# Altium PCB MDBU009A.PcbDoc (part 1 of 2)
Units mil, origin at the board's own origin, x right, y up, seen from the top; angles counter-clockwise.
Board outline 2000 x 3000 mil, 2 copper layers (Top Layer, Bottom Layer), stack 63.4 mil thick; 59 components, 52 nets, 252 pads, 189 vias.
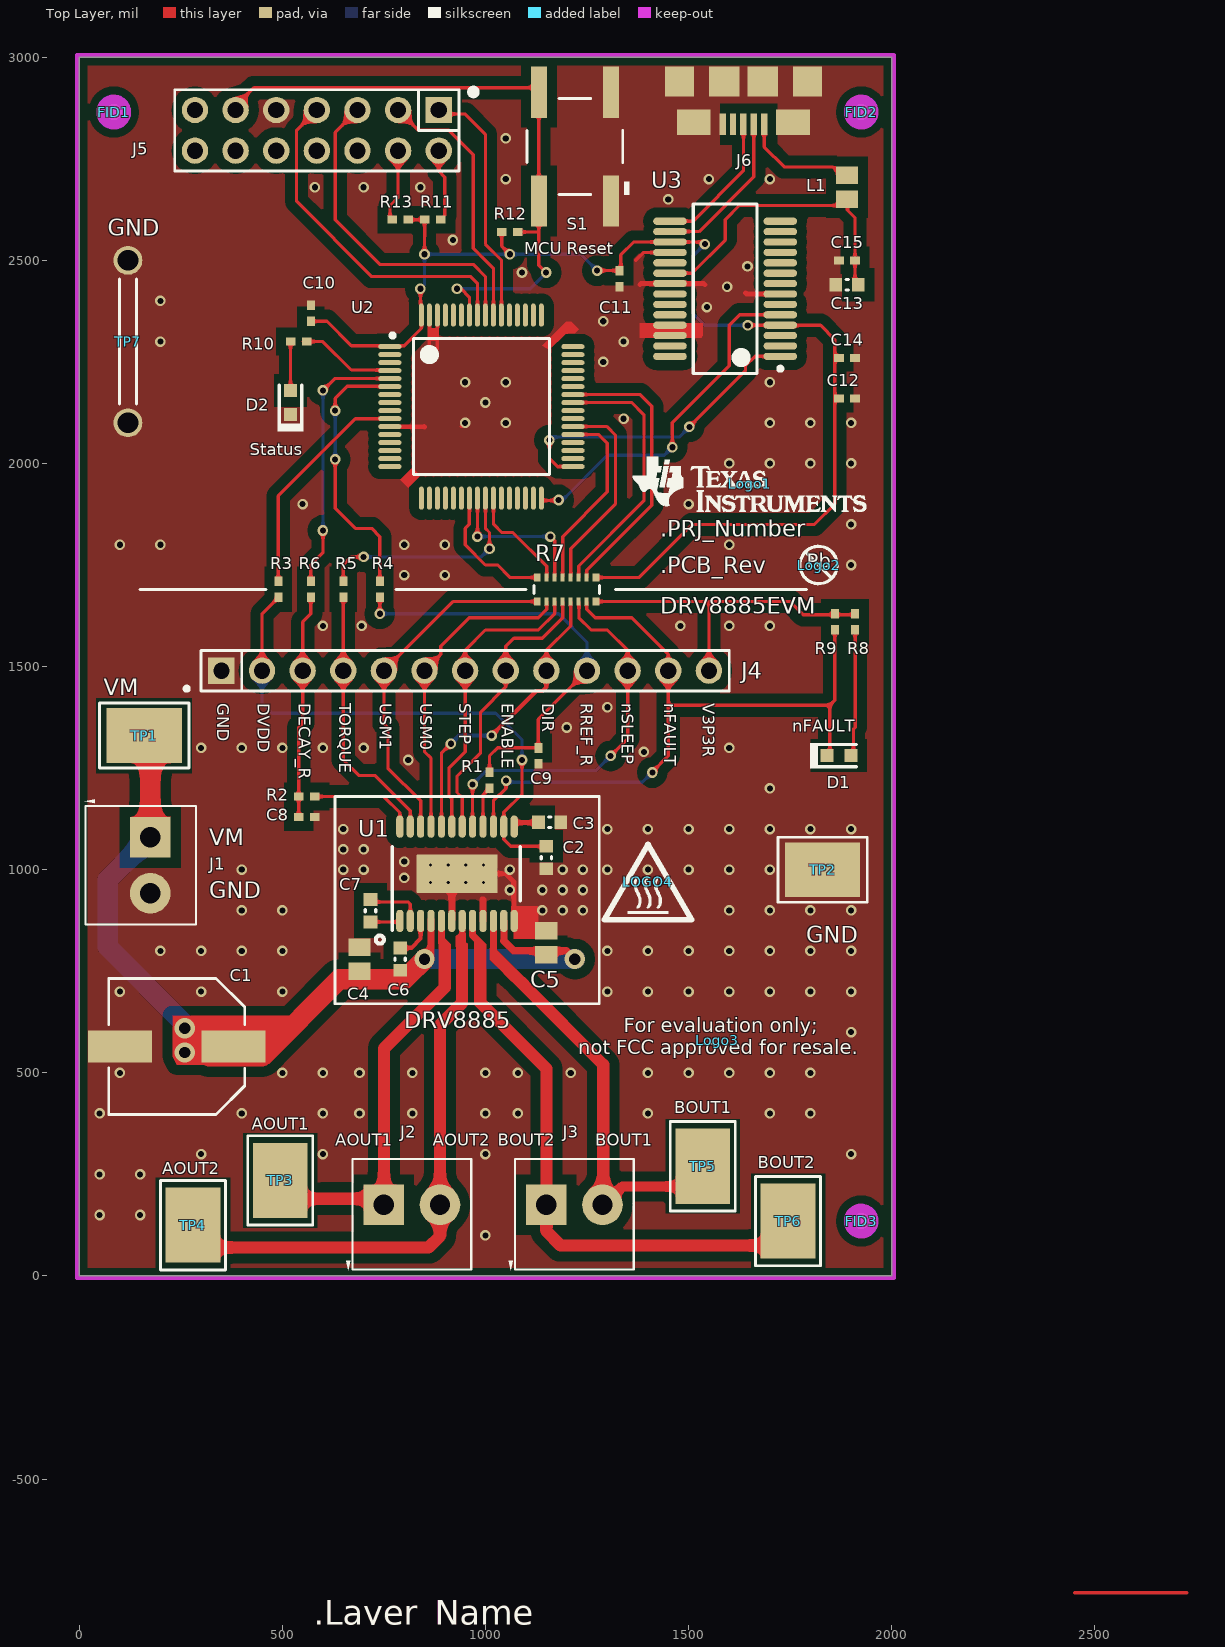
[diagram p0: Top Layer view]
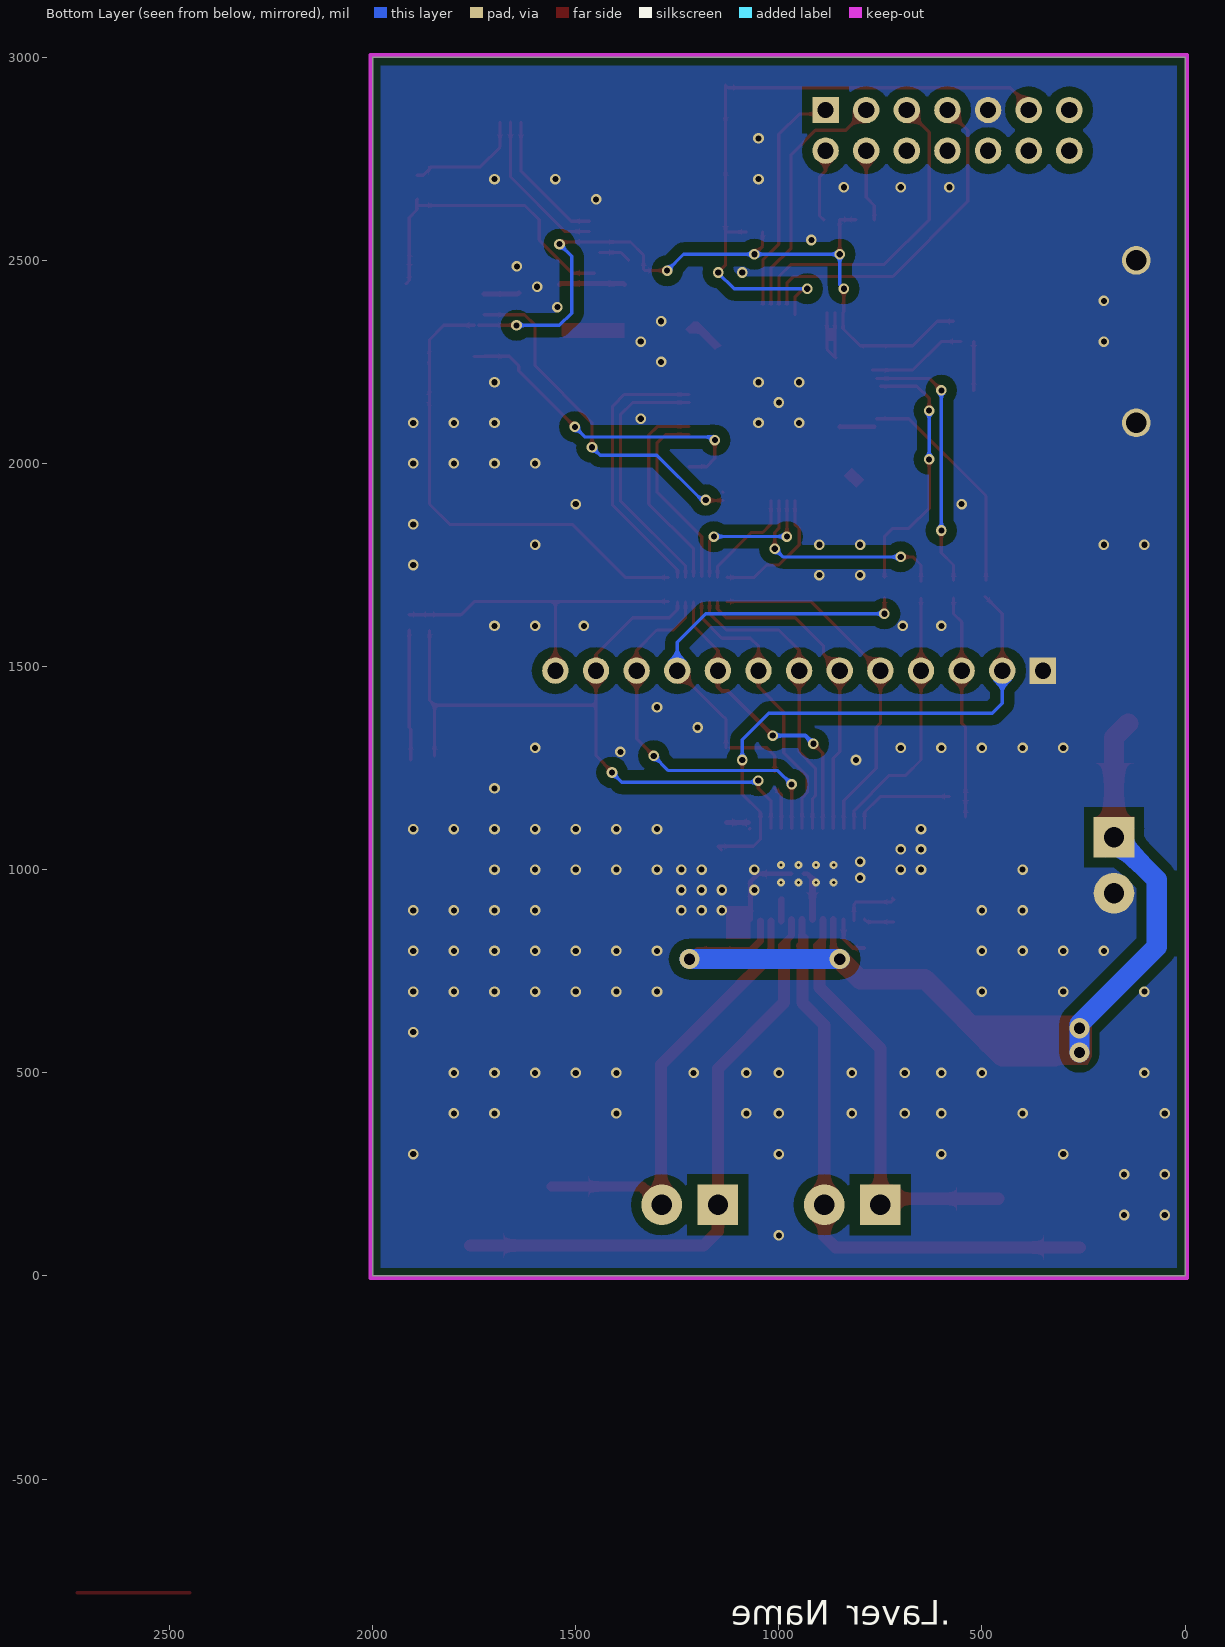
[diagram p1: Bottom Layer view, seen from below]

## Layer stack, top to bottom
Top Solder: solder mask 0.4, Solder Resist, Dk 3.5
Top Layer: signal copper 2.1
Dielectric1: core 59.2, FR-4, Dk 4.8
Bottom Layer: signal copper 2.1
Bottom Solder: solder mask 0.4, Solder Resist, Dk 3.5

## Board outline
0,0 0,3000 2000,3000 2000,0

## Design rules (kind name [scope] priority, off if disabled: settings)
AcuteAngle [All] p1: minimum=4.50000000000000E+0001 checktracksonly=FALSE
AssemblyTestPointUsage [All] p1: valid=2
Clearance Clearance_Keepouts [((IsTrack Or IsArc) And Not InPoly) And IsFree and IsKeepOut vs ((IsTrack Or IsArc) And Not InPoly) And IsFree and IsKeepOut] p1: gap=0
Clearance Clearance_BoardEdge_MountingHoles [OnCopper and InComponentClass('Mounting Holes') vs IsKeepOut] p2: gap=40
Clearance Clearance_BoardEdge_Poly [OnCopper and InPoly vs IsKeepOut] p3: gap=20
Clearance Clearance_BoardEdge [OnCopper and Not InComponentClass('Logo') and not InComponentClass('FiducialMark') and not InRegion(1000,500,4000,800) and Not IsKeepout vs IsKeepOut] p4: gap=20
Clearance Clearance_Poly [InPolygon] p5: gap=25
Clearance [All] p6: gap=7.87
ComponentClearance ComponentClearance_MountingHoles_FiducialMarks [InComponentClass('Mounting Holes') vs InComponentClass('FiducialMark')] p1: gap=50 collisioncheckmode=3 verticalgap=10 showdistances=FALSE
ComponentClearance ComponentClearance_Shunt [InComponentClass('Header') vs InComponentClass('Shunt')] p2: gap=0 collisioncheckmode=3 verticalgap=0 showdistances=FALSE
ComponentClearance ComponentClearance_Logo [InComponentClass('Logo')] p3: gap=50 collisioncheckmode=3 verticalgap=10 showdistances=FALSE
ComponentClearance ComponentClearance_ScrewToNut [(HasFootprint('NY PMS 440 0025 PH')) vs (HasFootprint('Keystone_1902C'))] p4: gap=5 collisioncheckmode=3 verticalgap=10 showdistances=FALSE
ComponentClearance ComponentClearance_MountingHoles [InComponentClass('Mounting Holes')] p5: gap=250 collisioncheckmode=3 verticalgap=100000 showdistances=FALSE
ComponentClearance ComponentClearance_SmallPassives [HasFootprint('0201*') or HasFootprint('0402*') or HasFootprint('0508') or HasFootprint('0603*') or HasFootprint('0612') or HasFootprint('0805*') or HasFootprint('0815*') or HasFootprint('0830*') or HasFootprint('1206*') or HasFootprint('1210*') or HasFootprint('1808*') or HasFootprint('1812*') or HasFootprint('1825*') or HasFootprint('2010*') or HasFootprint('2220*') or HasFootprint('2225*') or HasFootprint('2512*') or HasFootprint('2728*') or HasFootprint('3518*') vs HasFootprint('0201*') or HasFootprint('0402*') or HasFootprint('0508') or HasFootprint('0603*') or HasFootprint('0612') or HasFootprint('0805*') or HasFootprint('0815*') or HasFootprint('0830*') or HasFootprint('1206*') or HasFootprint('1210*') or HasFootprint('1808*') or HasFootprint('1812*') or HasFootprint('1825*') or HasFootprint('2010*') or HasFootprint('2220*') or HasFootprint('2225*') or HasFootprint('2512*') or HasFootprint('2728*') or HasFootprint('3518*')] p6: gap=20 collisioncheckmode=3 verticalgap=10 showdistances=FALSE
ComponentClearance ComponentClearance_THtoSMT [IsThruComponent vs IsSMTComponent] p7: gap=100 collisioncheckmode=3 verticalgap=30 showdistances=FALSE
ComponentClearance ComponentClearance_THtoTH [IsThruComponent vs IsThruComponent] p8: gap=118.11 collisioncheckmode=3 verticalgap=30 showdistances=FALSE
ComponentClearance [All] p9: gap=40 collisioncheckmode=3 verticalgap=10 showdistances=FALSE
DiffPairsRouting [All] p1: maxlimit=100 minlimit=10 mostfreqgap=10 toplayer_minwidth=15 toplayer_maxwidth=15 toplayer_prefwidth=15 bottomlayer_minwidth=15 bottomlayer_maxwidth=15 bottomlayer_prefwidth=15 maxuncoupledlength=1000
FabricationTestPointUsage TestPointUsage [All] p1: valid=2 allowmultiple=FALSE
FabricationTestpoint Testpoint [All] p1: side=3 testpointundercomponent=TRUE minsize=40 maxsize=100 preferedsize=60 minholesize=0 maxholesize=40 preferedholesize=32 testpointgrid=1 allowsidetop=TRUE allowsidebottom=TRUE usegrid=TRUE gridtolerance=0.01
FanoutControl Fanout_LCC [IsLCC] p1: bgadir=Out bgaviamode=Centered fanoutstyle=Auto fanoutdirection=Alternating viagrid=1 // Fanout_LCC (Default Rule)
FanoutControl Fanout_BGA [IsBGA] p2: bgadir=Out bgaviamode=Centered fanoutstyle=Auto fanoutdirection=Alternating viagrid=1 // Fanout_BGA (Default Rule)
FanoutControl Fanout_Default [All] p4: bgadir=Out bgaviamode=Centered fanoutstyle=Auto fanoutdirection=Alternating viagrid=1 // Fanout_Default (Default Rule)
FanoutControl Fanout_Small [(CompPinCount < 5)] p5: bgadir=Out bgaviamode=Centered fanoutstyle=Auto fanoutdirection=OutThenIn viagrid=1 // Fanout_Small (Default Rule)
HoleSize [All] p1: absolutevalues=TRUE maxlimit=251 minlimit=7.87 maxpercent=80.000 minpercent=20.000
MinimumAnnularRing MinimumAnnularRing_ThermalPadVias [IsVia and InAnyComponent] p1: minimumring=5.91
MinimumAnnularRing [All] p2: minimumring=5
MinimumSolderMaskSliver MinimumSolderMaskSliver_Logo [InComponentClass('Logo') vs InComponentClass('Logo')] p1: minsoldermaskwidth=0.7
MinimumSolderMaskSliver [All] p2: minsoldermaskwidth=3.94
PlaneConnect [All] p1: planeconnectstyle=Relief reliefexpansion=10 reliefentries=4 reliefconductorwidth=10 reliefairgap=10
PolygonConnect PolygonConnect_2 [All vs IsNamedPolygon('Bottom Layer-GND')] p1: connectstyle=Direct reliefconductorwidth=10 reliefentries=4 polygonreliefangle="90 Angle" airgapwidth=10
PolygonConnect PolygonConnect_1 [All vs IsNamedPolygon('Top Layer-GND')] p2: connectstyle=Direct reliefconductorwidth=10 reliefentries=4 polygonreliefangle="90 Angle" airgapwidth=10
PolygonConnect [All] p3: connectstyle=Relief reliefconductorwidth=10 reliefentries=4 polygonreliefangle="90 Angle" airgapwidth=10
RoutingVias ThermalPadVias [IsVia and InAnyComponent] p1: holewidth=7.87 width=19.68 viastyle="Through Hole" minholewidth=7.87 minwidth=19.68 maxholewidth=12.99 maxwidth=23.62
RoutingVias [All] p2: holewidth=16 width=34 viastyle="Through Hole" minholewidth=7.87 minwidth=26 maxholewidth=40 maxwidth=65
SilkToBoardRegionClearance [Not ((IsComment or IsDesignator) And (Hide <> 'False')) and not InRegion(1000,500,4000,800)] p1 off:
SilkToSilkClearance SilkToSilkClearance_Pb-FreeLogo [(HasFootprint('Pb-Free_Overlay_Medium') OR HasFootprint('Pb-Free_Overlay_Small')) vs (HasFootprint('Pb-Free_Overlay_Medium') OR HasFootprint('Pb-Free_Overlay_Small'))] p1: silktosilkclearance=0
SilkToSilkClearance [All] p2: silktosilkclearance=3
SilkToSolderMaskClearance "Silk to Solder Mask Opening" [All] p1: minsilkscreentomaskgap=2 clearancetoexposedcopper=FALSE
SolderMaskExpansion [All] p1: expansion=1.97
UnpouredPolygon [All] p1: allowunpoured=FALSE
Width [All] p1: maxlimit=100 minlimit=6 preferedwidth=10 checkconnectedcopper=TRUE
14 further rules are at their usual default settings.

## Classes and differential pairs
component class Header: J4
component class MDBU009A: C1 C2 C3 C4 C5 C6 C7 C8 C9 D1 J1 J2 J3 J4 R1 R2 R3 R4 R5 R6 R7 R8 R9 TP1 TP2 TP3 TP4 TP5 TP6 TP7
component class MDBU009A_MSP430F2617: C10 C11 C12 C13 C14 C15 D2 J5 J6 L1 R10 R11 R12 R13 S1 U2 U3
component class Logo: Logo1
component class MDBU009A_Hardware: FID1 FID2 FID3 Logo1 Logo2 Logo3 LOGO4 ZZ1 ZZ2 ZZ3 ZZ4
component class FiducialMark: FID1 FID2 FID3
component class AssemblyNote: ZZ1 ZZ2 ZZ3 ZZ4

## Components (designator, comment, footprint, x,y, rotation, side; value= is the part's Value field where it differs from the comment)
C1 "EEE-FK1H101P" SM_RADIAL_F 240,565 r180 top
C2 "C0603C474K9RACTU" 0603L 1150,1030 r90 top
C3 "C0603C474K9RACTU" 0603L 1158,1117 r180 top
C4 "C2012X7R2A103K" 0805L 690,780 r270 top
C5 "C2012X7R2A103K" 0805L 1150,820 r270 top
C6 "GRM188R71E224KA88D" 0603L 790,780 r90 top
C7 "C1608X7R2A223K" 0603L 717,899 r270 top
C8 "GRM155R71E103KA01D" 0402L 560,1130 r0 top
C9 "GRM155R71E103KA01D" 0402L 1130,1280 r270 top
C10 "GRM155R61A104KA01D" 0402L 570,2370 r90 top
C11 "GRM155R61A104KA01D" 0402L 1330,2455 r270 top
C12 "GRM155R61A104KA01D" 0402L 1890,2160 r0 top
C13 "CGB3B1X5R1A475K055AC" 0603L 1890,2440 r180 top
C14 "GRM155R61A105KE15D" 0402L 1890,2260 r0 top
C15 "GRM155R61A104KA01D" 0402L 1890,2500 r180 top
D1 "LTST-C190CKT" LED_LTST-C190_Red 1870,1281 r180 top
D2 "LTST-C190GKT" LED_LTST-C190 520,2150 r270 top
FID1 "Fiducial" Fiducial10-20 85,2865 r90 top
FID2 "Fiducial" Fiducial10-20 1925,2865 r90 top
FID3 "Fiducial" Fiducial10-20 1925,135 r90 top
J1 "ED555/2DS" TERM_BLK_ED555-2DS 175,1080 r270 top
J2 "ED555/2DS" TERM_BLK_ED555-2DS 750,175 r0 top
J3 "ED555/2DS" TERM_BLK_ED555-2DS 1150,175 r0 top
J4 "TSW-113-07-G-S" TSW-113-07-G-S 950,1490 r0 top
J5 "PEC07DAAN" CONN_PEC07DAAN 585,2820 r180 top
J6 "ZX62-B-5PA(11)" CONN_USB_micro_ZX62-B-5PA 1635,2835 r180 top
L1 "BKP2125HS600-T" 0805L 1890,2680 r90 top
Logo1 "Texas Instruments" TI_Stacked_Overlay_Small_Vertical 1650,1950 r270 top
Logo2 "Pb-Free Symbol" Pb-Free_Overlay_Small 1820,1750 r0 top
Logo3 "FCC disclaimer" FCC_disclaimer_stacked 1570,580 r0 top
LOGO4 "CAUTION HOT SURFACE" IEC_HotSurface_Small 1400,970 r0 top
R1 "CRCW040220K0FKED" 0402L 1010,1220 r270 top
R2 "CRCW04024K99FKED" 0402L 560,1180 r180 top
R3 "ERJ-2GE0R00X" 0402L 490,1690 r90 top
R4 "ERJ-2GE0R00X" 0402L 740,1690 r90 top
R5 "ERJ-2GE0R00X" 0402L 650,1690 r90 top
R6 "ERJ-2GE0R00X" 0402L 570,1690 r90 top
R7 "EXB-2HVR000V" RESCAXS_EXB-2HV 1200,1690 r0 top
R8 "CRCW0402510RJNED" 0402L 1910,1610 r90 top
R9 "CRCW04024K99FKED" 0402L 1860,1610 r90 top
R10 "CRCW0402330RJNED" 0402L 540,2300 r0 top
R11 "ERJ-2GE0R00X" 0402L 870,2600 r0 top
R12 "CRCW04023K32FKED" 0402L 1060,2570 r180 top
R13 "ERJ-2GE0R00X" 0402L 790,2600 r180 top
S1 "EVQP1D05M" SW_EVQxxx05M 1220,2780 r180 top
TP1 "5016" Testpoint_Keystone_Compact 160,1330 r0 top
TP2 "5016" Testpoint_Keystone_Compact 1830,1000 r180 top
TP3 "5016" Testpoint_Keystone_Compact 495,235 r90 top
TP4 "5016" Testpoint_Keystone_Compact 280,125 r90 top
TP5 "5016" Testpoint_Keystone_Compact 1535,270 r90 top
TP6 "5016" Testpoint_Keystone_Compact 1745,135 r90 top
TP7 "D3082-05" Harwin_D3082-05 120,2300 r270 top
U1 "DRV8885PWPR" PWP0024B_N 930,990 r90 top
U2 "MSP430F2617TPM" PM0064A_N 990,2140 r0 top
U3 "FT232RL" SSOP28_N 1590,2430 r180 top
ZZ1 "These assemblies are ESD sensitive, ESD precautions shall be observed." AssemblyNote 180,3500 r0 top
ZZ2 "These assemblies must be clean and free from flux and all contaminants. Use of no clean flux is not acceptable." AssemblyNote 180,3400 r0 top
ZZ3 "These assemblies must comply with workmanship standards IPC-A-610 Class 2, unless otherwise specified." AssemblyNote 180,3300 r0 top
ZZ4 "Shorting plug TP7 shall be raised to minimum height of 250mils above PCB" AssemblyNote 180,3200 r0 top

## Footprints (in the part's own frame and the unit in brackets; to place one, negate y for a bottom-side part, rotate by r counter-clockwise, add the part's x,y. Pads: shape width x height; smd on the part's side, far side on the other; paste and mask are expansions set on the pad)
0402L [mm] "0402 from SM-752 data"
  rect 0.6x0.5 smd: 1(-0.5,0) 2(0.5,0)
  body extent -0.55,-0.3 0.55,0.3, height 0.6
0603L [mm] "0603 from SM-752 data"
  rect 0.8x0.85 smd: 1(-0.7,0) 2(0.7,0)
  silkscreen extent -0.07,-0.33 0.07,0.33, body extent -0.87,-0.47 0.87,0.47, height 1
0805L [mm] "0805 from SM-752 data"
  rect 1.1x1.4 smd: 1(-0.75,0) 2(0.75,0)
  body extent -1.1,-0.72 1.1,0.72, height 1.45
AssemblyNote [mil] "Assembly Note"
CONN_PEC07DAAN [mm] "SULLINS"
  rect 1.65x1.65 hole 1.016 mask+0: 1(-7.62,-1.27)
  round 1.65 hole 1.016 mask+0: 2(-7.62,1.27) 3(-5.08,-1.27) 4(-5.08,1.27) 5(-2.54,-1.27) 6(-2.54,1.27) 7(0,-1.27) 8(0,1.27) 9(2.54,-1.27) 10(2.54,1.27) 11(5.08,-1.27) 12(5.08,1.27) 13(7.62,-1.27) 14(7.62,1.27)
  silkscreen extent -9.99,-2.6 8.89,2.54, body extent -8.95,-2.6 8.95,2.6, height 11.43
CONN_USB_micro_ZX62-B-5PA [mm] "Hirose"
  rect 0.4x1.35 smd: 1(-1.3,0) 2(-0.65,0) 3(0,0) 4(0.65,0) 5(1.3,0)
  rect 1.9x1.9 smd: 6(-1.2,-2.675) 7(1.2,-2.675)
  rect 1.8x1.9 smd: 8(-4,-2.675) 9(4,-2.675)
  rect 2.1x1.6 smd: 10(-3.1,-0.125) 11(3.1,-0.125)
  body extent -3.75,-5.33 3.75,0.18, height 2.55
FCC_disclaimer_stacked [mil]
Fiducial10-20 [mm]
  round 1 smd mask+0.5: 1(0,0)
  Top Layer keep-out circle w1.178: c0,0 r0.5
Harwin_D3082-05 [mm] "Shorting Plug, 10.16mm spacing, TH"
  round 1.8 hole 1.3: 1(-5.08,0) 2(5.08,0)
  silkscreen extent -3.9,-0.53 3.9,0.53, body extent -5.6,-0.52 5.61,0.52, height 6.63
IEC_HotSurface_Small [mil]
  silkscreen extent -107,-93 107,92
LED_LTST-C190 [mm] "Lite-On"
  rect 0.8x0.8 smd: 1(-0.75,0) 2(0.75,0)
  silkscreen extent -1.1,-0.8 1.8,0.8, body extent -0.85,-0.45 0.85,0.45, height 0.9
LED_LTST-C190_Red [mm] "Lite-On"
  rect 0.8x0.8 smd: 1(-0.75,0) 2(0.75,0)
  silkscreen extent -1.1,-0.8 1.8,0.8, body extent -0.85,-0.45 0.85,0.45, height 0.9
Pb-Free_Overlay_Small [mil]
  silkscreen extent -46,-46 46,46
PM0064A_N [mm] "Thin QFP, 64-Leads, Body 10x10mm, Pitch 0.5mm, IPC Medium Density"
  oval 1.45x0.3 smd: 1(-5.725,3.75) 2(-5.725,3.25) 3(-5.725,2.75) 4(-5.725,2.25) 5(-5.725,1.75) 6(-5.725,1.25) 7(-5.725,0.75) 8(-5.725,0.25) 9(-5.725,-0.25) 10(-5.725,-0.75) 11(-5.725,-1.25) 12(-5.725,-1.75) 13(-5.725,-2.25) 14(-5.725,-2.75) 15(-5.725,-3.25) 16(-5.725,-3.75) 33(5.725,-3.75) 34(5.725,-3.25) 35(5.725,-2.75) 36(5.725,-2.25) 37(5.725,-1.75) 38(5.725,-1.25) 39(5.725,-0.75) 40(5.725,-0.25) 41(5.725,0.25) 42(5.725,0.75) 43(5.725,1.25) 44(5.725,1.75) 45(5.725,2.25) 46(5.725,2.75) 47(5.725,3.25) 48(5.725,3.75)
  oval 0.3x1.45 smd: 17(-3.75,-5.725) 18(-3.25,-5.725) 19(-2.75,-5.725) 20(-2.25,-5.725) 21(-1.75,-5.725) 22(-1.25,-5.725) 23(-0.75,-5.725) 24(-0.25,-5.725) 25(0.25,-5.725) 26(0.75,-5.725) 27(1.25,-5.725) 28(1.75,-5.725) 29(2.25,-5.725) 30(2.75,-5.725) 31(3.25,-5.725) 32(3.75,-5.725) 49(3.75,5.725) 50(3.25,5.725) 51(2.75,5.725) 52(2.25,5.725) 53(1.75,5.725) 54(1.25,5.725) 55(0.75,5.725) 56(0.25,5.725) 57(-0.25,5.725) 58(-0.75,5.725) 59(-1.25,5.725) 60(-1.75,5.725) 61(-2.25,5.725) 62(-2.75,5.725) 63(-3.25,5.725) 64(-3.75,5.725)
  silkscreen extent -5.67,-4.25 4.25,4.57, body extent -6,-6 6,6, height 1.49
PWP0024B_N [mm] "TSOP, 24-Leads, Body 7.9x4.5mm (max), Pitch 0.65mm, IPC Medium Density"
  rrect100% 1.4x0.45 smd: 1(-2.95,3.575) 2(-2.95,2.925) 3(-2.95,2.275) 4(-2.95,1.625) 5(-2.95,0.975) 6(-2.95,0.325) 7(-2.95,-0.325) 8(-2.95,-0.975) 9(-2.95,-1.625) 10(-2.95,-2.275) 11(-2.95,-2.925) 12(-2.95,-3.575) 13(2.95,-3.575) 14(2.95,-2.925) 15(2.95,-2.275) 16(2.95,-1.625) 17(2.95,-0.975) 18(2.95,-0.325) 19(2.95,0.325) 20(2.95,0.975) 21(2.95,1.625) 22(2.95,2.275) 23(2.95,2.925) 24(2.95,3.575)
  rrect4% 2.4x5.07 smd mask+0.085: 25(0,0)
  silkscreen extent -3.55,-3.95 1.7,4.05, body extent -3.21,-3.9 3.21,3.9, height 1.2
RESCAXS_EXB-2HV [mm] "Panasonic Resistor Array"
  rect 0.425x0.5 smd mask+0.07: 1(-1.837,-0.75) 8(1.837,-0.75) 9(1.837,0.75) 16(-1.837,0.75)
  rect 0.25x0.5 smd mask+0.07: 2(-1.25,-0.75) 3(-0.75,-0.75) 4(-0.25,-0.75) 5(0.25,-0.75) 6(0.75,-0.75) 7(1.25,-0.75) 10(1.25,0.75) 11(0.75,0.75) 12(0.25,0.75) 13(-0.25,0.75) 14(-0.75,0.75) 15(-1.25,0.75)
  silkscreen extent -2.05,-0.25 2.05,0.25, body extent -1.95,-0.8 1.95,0.8, height 0.55
SM_RADIAL_F [mm] "8 x 10.2mm:  Panasonic F"
  rect 4x2 smd: 1(-3.55,0) 2(3.55,0)
  silkscreen extent -4.25,-4.25 4.25,4.25, body extent -4.26,-4.26 4.26,4.26, height 10.5
SSOP28_N [mm] "SOP, 28-Leads, Body 10.2x5.3mm, Pitch 0.65mm, IPC Medium Density"
  oval 2.1x0.45 smd: 1(-3.45,4.225) 2(-3.45,3.575) 3(-3.45,2.925) 4(-3.45,2.275) 5(-3.45,1.625) 6(-3.45,0.975) 7(-3.45,0.325) 8(-3.45,-0.325) 9(-3.45,-0.975) 10(-3.45,-1.625) 11(-3.45,-2.275) 12(-3.45,-2.925) 13(-3.45,-3.575) 14(-3.45,-4.225) 15(3.45,-4.225) 16(3.45,-3.575) 17(3.45,-2.925) 18(3.45,-2.275) 19(3.45,-1.625) 20(3.45,-0.975) 21(3.45,-0.325) 22(3.45,0.325) 23(3.45,0.975) 24(3.45,1.625) 25(3.45,2.275) 26(3.45,2.925) 27(3.45,3.575) 28(3.45,4.225)
  silkscreen extent -3.57,-5.3 2,5.3, body extent -2.7,-5.3 2.7,5.3, height 2
SW_EVQxxx05M [mm] "Panasonic EVQP0/EVQP1/EVQ9P 6mm Square Long Travel Light Touch Switch"
  rect 1x3.2 smd: 1(-2.25,3.4) 2(-2.25,-3.4) 3(2.25,-3.4) 4(2.25,3.4)
  silkscreen extent -3.4,-3 3,3, body extent -3,-3 3,3, height 5
TERM_BLK_ED555-2DS [mil]
  rect 100x100 hole 50: 1(0,0)
  round 100 hole 50: 2(138,0)
  silkscreen extent -93,-161 215,113, body extent -69,-150 207,106, height 323
Testpoint_Keystone_Compact [mil] "Compact SMT test point"
  rect 185x135 smd: 1(0,0)
  silkscreen extent -110,-80 110,80, body extent -75,-56 75,56, height 91
TI_Stacked_Overlay_Small_Vertical [mil]
  silkscreen extent -66,-288 69,288
TSW-113-07-G-S [mm] "Samtec 100mil, 1x13, 230 mil above insulator"
  rect 1.65x1.65 hole 1.016 mask+0: 1(-15.24,0)
  round 1.65 hole 1.016 mask+0: 2(-12.7,0) 3(-10.16,0) 4(-7.62,0) 5(-5.08,0) 6(-2.54,0) 7(0,0) 8(2.54,0) 9(5.08,0) 10(7.62,0) 11(10.16,0) 12(12.7,0) 13(15.24,0)
  silkscreen extent -17.53,-1.27 16.51,1.27, body extent -16.51,-1.27 16.51,1.27, height 8.38

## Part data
C1: "CAP, AL, 100 µF, 50 V, +/- 20%, 0.34 ohm, SMD"
C2 C3: "CAP, CERM, 0.47 µF, 6.3 V, +/- 10%, X7R, 0603"
C4 C5: "CAP, CERM, 0.01 µF, 100 V, +/- 10%, X7R, 0805"
C6: "CAP, CERM, 0.22 µF, 25 V, +/- 10%, X7R, 0603"
C7: "CAP, CERM, 0.022 µF, 100 V, +/- 10%, X7R, 0603"
C8 C9: "CAP, CERM, 0.01 µF, 25 V, +/- 10%, X7R, 0402"
C10 C11 C12 C15: "CAP, CERM, 0.1uF, 10V, +/-10%, X5R, 0402"
C13: "CAP, CERM, 4.7uF, 10V, +/-10%, X5R, 0603"
C14: "CAP, CERM, 1uF, 10V, +/-10%, X5R, 0402"
D1: "LED, Red, SMD"
D2: "LED, Green, SMD"
FID1 FID2 FID3: "Fiducial mark.  There is nothing to buy or mount."
J1 J2 J3: "Terminal Block, 6A, 3.5mm Pitch, 2-Pos, TH"
J4: "Header, 100mil, 13x1, Gold, TH"
J5: "Header, 100mil, 7x2, Tin plated, TH"
J6: "Connector, micro USB Type B, Receptacle, R/A, SMD"
L1: "Ferrite Bead, 60 ohm @ 100 MHz, 3 A, 0805"
Logo1: library part TI_Logo, "Texas Instrument Corporate Signature"
Logo2: library part Pb-Free
Logo3: library part FCC_disclaimer, "FCC_disclaimer"
LOGO4: library part IEC_HotSurface, "IEC 61010-1 Hot Surface Warning"
R1: "RES, 20.0 k, 1%, 0.063 W, 0402"
R2 R9: "RES, 4.99k ohm, 1%, 0.063W, 0402"
R3 R4 R5 R6: "RES, 0, 5%, 0.063 W, 0402"
R7: "RES, 0, 5%, 0.0625 W, Resistor Array - 8x1"
R8: "RES, 510 ohm, 5%, 0.063W, 0402"
R10: "RES, 330 ohm, 5%, 0.063W, 0402"
R11 R13: "RES, 0 ohm, 5%, 0.063W, 0402"
R12: "RES, 3.32k ohm, 1%, 0.063W, 0402"
S1: "Switch, Tactile, SPST-NO, 0.05A, 12V, SMT"
TP1 TP2 TP3 TP4 TP5 TP6: "Test Point, Compact, SMT"
TP7: "1mm Uninsulated Shorting Plug, 10.16mm spacing, TH"
U1: "1.5 A Stepper Motor Driver with STEP / DIR Interface, PWP0024B"
U2: "16 MHz Mixed Signal Microcontroller with 92 KB Flash, 8192 B SRAM and 48 GPIOs, -40 to 105 degC, 64-pin QFP (PM), Green (RoHS & no Sb/Br)"
U3: "USB to Serial UART, SSOP28"
ZZ1 ZZ2 ZZ3 ZZ4: library part AssemblyNote

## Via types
v1: diameter 26, hole 15, Top Layer to Bottom Layer, tented both sides, 177 vias
v2: diameter 19.68, hole 7.87, Top Layer to Bottom Layer, 8 vias
v3: diameter 50, hole 28, Top Layer to Bottom Layer, tented both sides, 4 vias

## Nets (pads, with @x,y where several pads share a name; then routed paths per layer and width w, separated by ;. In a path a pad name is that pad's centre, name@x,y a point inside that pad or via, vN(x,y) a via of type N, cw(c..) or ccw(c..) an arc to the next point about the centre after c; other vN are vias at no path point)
AOUT1: J2.1 TP3.1 U1.5 | length 1033.4
  Top Layer w17: U1.5@891.61,877.8 891.61,828.39 900,820
  Top Layer w30: TP3.1@460,190 750,190 750,560 900,710 900,810
AOUT2: J2.2 TP4.1 U1.7 | length 1495.9
  Top Layer w17: 942.8,757.2 U1.7@942.8,877.8
  Top Layer w30: TP4.1@258.69,70 860,70 888,98 888,618 942,672 942,810
AVDD: C3.2 U1.13 | length 58.5
  Top Layer w8: U1.13@1070.75,1102.2 U1.13@1072.95,1100
  Top Layer w12: U1.13@1074,1116 C3.2@1129.37,1116
BOUT1: J3.2 TP5.1 U1.10 | length 1109.1
  Top Layer w16: 1019.57,790.43 1040,770
  Top Layer w17: 1019.57,790.43 U1.10@1019.57,873.86
  Top Layer w25: J3.2@1290,173 1337,220 TP5.1@1560,220
  Top Layer w30: 1035.5,774.5 1074.2,735.8 1074.83,735.8 1095.8,714.83 1095.8,714.2 1290,520 J3.2@1290,173
BOUT2: J3.1 TP6.1 U1.8 | length 1413.3
  Top Layer w16: 984,818 984,822
  Top Layer w17: U1.8@968.39,877.8 968.39,837.61 984,822
  Top Layer w18: 984,800 984,818
  Top Layer w30: 987,797 987,673 1150,510 1150,225 ; J3.1@1150,175 1150,110 1185,75 TP6.1@1760,75
DECAY: R2.1 U1.24 | length 264.4
  Top Layer w8: R2.1@579.68,1180 750,1180 789.25,1140.75 U1.24@789.25,1102.2
DECAY_R: C8.1 J4.3 R2.2 R6.1 | length 550.6
  Top Layer w8: C8.1@540.32,1130 540.31,1350.31 550,1360 J4.3@550,1490 550,1610 570,1630 R6.1@570,1668.35
DIR: J4.9 R7.5 U1.20 | length 743.8
  Top Layer w8: U1.20@891.61,1102.2 891.61,1286.61 v1(915,1310) ; J4.9@1150,1490 1150,1540 1209.84,1599.84 R7.5@1209.84,1658.5
  Top Layer w10: v1(1015,1330) 1125,1440 1140,1440 1150,1450 J4.9@1150,1490
  Bottom Layer w10: v1(915,1310) 935,1330 v1(1015,1330)
DM: J6.2 U3.16 | length 384.9
  Top Layer w8: U3.16@1465.9,2570.8 1525.8,2570.8 1660.59,2705.59 J6.2@1660.59,2840
DP: J6.3 U3.15 | length 340.3
  Top Layer w8: U3.15@1465.9,2596.4 1511.4,2596.4 1635,2720 J6.3@1635,2840
DVDD: C2.2 J4.2 R3.1 U1.14 | length 1344.9
  Top Layer w8: J4.2@450,1490 450,1630 R3.1@492.28,1672.28 ; v1(1090,1270) 1090,1186 1045.16,1141.16 1045.16,1102.2 1045.16,1074.84 1062.44,1057.56 C2.2@1150,1057.56 C2.2@1141.44,1049
  Bottom Layer w8: J4.2@450,1490 450,1410 474.8,1385.2 1010,1385.2 1024.82,1385.18 1090,1320 v1(1090,1270)
ENABLE: J4.8 R7.4 U1.18 | length 710.4
  Top Layer w8: U1.18@942.8,1102.2 942.8,1177.2 930,1190 930,1230 988,1288 988,1388 1050,1450 J4.8@1050,1490 1050,1550 1070,1570 1140,1570 1190.16,1620.16 R7.4@1190.16,1658.5
GND: C1.2 C2.1 C3.1 C4.1 C5.1 C8.2 C9.2 C10.2 C11.2 C12.2 C13.2 C14.2 C15.2 D2.2 J1.2 J4.1 J5.9 J6.5 J6.6 J6.7 J6.8 J6.9 J6.10 J6.11 S1.1 S1.2 TP2.1 TP7.1 TP7.2 U1.6 U1.9 U1.12 U1.25 U2.11 U2.62 U2.63 U3.7 U3.18 U3.21 U3.25 U3.26 | length 1040
  Top Layer w8: 860,2260 861.9,2261.9 ; U2.63@861.9,2371 861.9,2261.9 ; U2.62@881.6,2371 881.6,2281.6 861.9,2261.9 ; 940.7,2090.7 v1(950,2100) ; 990,930 993.98,926.02 ; 1370,2500 1389.6,2519.6 U3.18@1440.9,2519.6
  Top Layer w11: U2.11@764.61,2090.79 849.21,2090.79
  Top Layer w12: 849.21,2090.79 850,2090 ; U1.25@917.2,977.2 U1.25@930,990 U1.25@938,990 ; U1.25@970,990 1050,990 1070,970 U1.12@1070,877.8 ; 1380,2440 1382.8,2442.8 U3.21@1454.17,2442.8 1537.2,2442.8 1540,2440 ; 1640,2420 1642.8,2417.2 U3.7@1725.83,2417.2
  Top Layer w17: U1.6@917.2,877.8 U1.25@917.2,977.2 ; U1.9@993.98,873.86 993.98,926.02
  other v1: 1000,100 50,150 150,150 50,250 150,250 300,300 600,300 1000,300 1900,300 50,400 400,400 600,400 690,400 820,400 1000,400 1080,400 1400,400 1700,400 1800,400 100,500 500,500 600,500 690,500 820,500 1000,500 1080,500 1210,500 1400,500 1500,500 1600,500 1700,500 1800,500 1900,600 100,700 300,700 500,700 1300,700 1400,700 1500,700 1600,700 1700,700 1800,700 1900,700 200,800 300,800 400,800 500,800 1300,800 1400,800 1500,800 1600,800 1700,800 1800,800 1900,800 400,900 500,900 1140,900 1190,900 1240,900 1600,900 1700,900 1800,900 1900,900 1060,950 1140,950 1190,950 1240,950 800,980 400,1000 650,1000 700,1000 1060,1000 1190,1000 1240,1000 1300,1000 1400,1000 1500,1000 1600,1000 1700,1000 800,1020 650,1050 700,1050 650,1100 1300,1100 1400,1100 1500,1100 1600,1100 1700,1100 1800,1100 1900,1100 1700,1200 810,1270 1390,1290 300,1300 400,1300 500,1300 600,1300 700,1300 1600,1300 1200,1350 1300,1400 600,1600 695,1600 1480,1600 1600,1600 1700,1600 800,1725 900,1725 1900,1750 100,1800 200,1800 800,1800 900,1800 1600,1800 1900,1850 550,1900 1500,1900 1600,2000 1700,2000 1800,2000 1900,2000 1050,2100 1700,2100 1800,2100 1900,2100 1340,2110 1000,2150 950,2200 1050,2200 1700,2200 1290,2250 200,2300 1340,2300 1290,2350 1545,2385 200,2400 1595,2435 1090,2470 1645,2485 920,2550 1450,2650 580,2680 700,2680 840,2680 1050,2700 1550,2700 1700,2700 1050,2800
  other v2: 865.04,968.35 908.35,968.35 951.65,968.35 994.96,968.35 865.04,1011.65 908.35,1011.65 951.65,1011.65 994.96,1011.65
MSP_DECAY: R6.2 U2.5 | length 646.6
  Top Layer w8: R6.2@570,1711.65 570,1750 600,1780 v1@600,1830 ; v1(600,2180) 628.9,2208.9 U2.5@758.9,2208.9
  Bottom Layer w8: v1(600,1835) v1(600,2180)
MSP_DIR: R7.12 U2.38 | length 501.7
  Top Layer w8: R7.12@1210,1721.5 1210,1790 1320,1900 1320,2070 1299.3,2090.7 U2.38@1220.9,2090.7
MSP_DVDD: R3.2 U2.10 | length 555.9
  Top Layer w8: R3.2@490,1711.65 490,1920 680,2110 U2.10@758.9,2110
MSP_ENABLE: R7.13 U2.37 | length 461.9
  Top Layer w8: R7.13@1190,1721.5 1190,1820 1300,1930 1300,2050 1279,2071 U2.37@1220.9,2071
MSP_NFAULT: R7.10 U2.42 | length 687.9
  Top Layer w8: U2.42@1220.9,2170 1380,2170 1409.21,2140.79 1409.21,1897.21 1249.21,1737.21 R7.10@1249.21,1719.53
MSP_NSLEEP: R7.11 U2.41 | length 649.4
  Top Layer w8: U2.41@1220,2150 1360,2150 1390,2120 1390,1908 1229.53,1747.53 R7.11@1229.53,1719.53
MSP_RREF: R4.2 U2.6 | length 641.4
  Top Layer w8: v1(630,2010) 630,1890 680,1840 720,1840 740,1820 R4.2@740,1720 ; v1(630,2130) 630,2160 660,2190 U2.6@750,2190
  Bottom Layer w8: v1(630,2010) v1(630,2130)
MSP_STEP: R7.14 U2.24 | length 371.8
  Top Layer w8: v1@980.1,1820 U2.24@980.1,1909 ; v1(1160,1820) 1170.47,1809.53 R7.14@1170.47,1721.5
  Bottom Layer w8: v1(980,1820) v1(1160,1820)
MSP_TORQUE: R5.2 U2.25 | length 540.1
  Top Layer w8: R5.2@650,1709.69 650,1750 670,1770 v1(700,1770) ; U2.25@999.8,1909 999.8,1840.2 1010,1830 v1(1010,1790)
  Bottom Layer w8: v1(700,1770) 990,1770 v1(1010,1790)
MSP_USM0: R7.15 U2.26 | length 259.8
  Top Layer w8: 1019.5,1850 U2.26@1019.5,1909 ; 1020,1850 1040,1830 1067.66,1830 1150.79,1746.87 R7.15@1150.79,1719.53
MSP_USM1: R7.16 U2.23 | length 325.2
  Top Layer w8: U2.23@960.4,1909 960.4,1850.4 950,1840 950,1800 1000,1750 1030,1750 1060,1720 1060,1719.53 R7.16@1127.66,1719.53 R7.16@1127.19,1720
NetC6_2: C6.2 U1.3 | length 107.3
  Top Layer w10: C6.2@790,807.56 817.56,807.56 840.43,830.43 U1.3@840.43,877.8
NetC7_1: C7.1 U1.2 | length 148.7
  Top Layer w8: C7.1@720.44,930 C7.1@717,926.56 722.91,920.65 809.35,920.65 814.84,915.16 U1.2@814.84,873.86
NetC7_2: C7.2 U1.1 | length 74.9
  Top Layer w8: C7.2@717,871.44 782.9,871.44 U1.1@789.25,877.8
NetC13_1: C13.1 C15.1 L1.1 U3.20 | length 754.7
  Top Layer w8: U3.20@1454.17,2468.39 1508.39,2468.39 1590,2550 1590,2600 1625,2635 L1.1@1891.1,2635 ; L1.1@1890,2650.47 1891.1,2649.37 L1.1@1891.1,2635 ; C13.1@1917.56,2442.44 1909.68,2450.32 C15.1@1909.68,2500 1909.68,2605.31 1891.1,2623.9 L1.1@1891.1,2635
NetD1_1: D1.1 R8.1 | length 321.3
  Top Layer w8: D1.1@1905.8,1270.8 1905.8,1345.8 1910,1350 R8.1@1910,1590.32
NetD2_1: D2.1 R10.1 | length 120.6
  Top Layer w8: D2.1@520,2179.53 520.32,2179.84 R10.1@520.32,2300
NetJ5_2: J5.2 R11.2 | length 180.5
  Top Layer w8: J5.2@885,2770 885,2720 900,2705 900,2610.31 R11.2@889.69,2600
